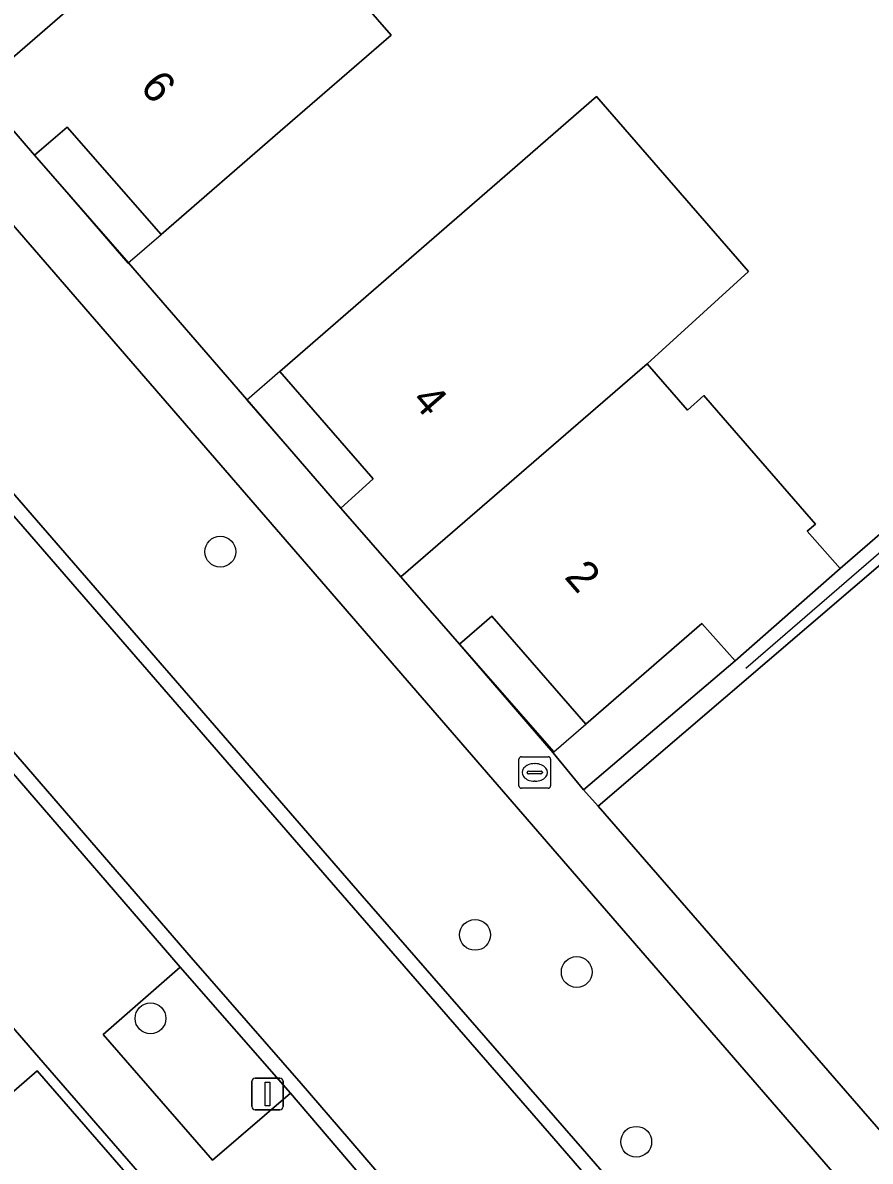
# Model space of a CAD drawing. Extents: x 155887 to 156869, y 383880 to 384678.
# Drawn here: x 156249.09 to 156275.97, y 384107.68 to 384143.78 of the extents above; entities that cross this region are included whole.
import ezdxf

# ---------------------------------------------------------------- set-up
doc = ezdxf.new("R2010")
doc.units = 0
for name, color, linetype in [('IMGEO_Berm_groen', 7, 'Continuous'), ('IMGEO_Boom', 7, 'Continuous'), ('IMGEO_Brandkraan', 7, 'Continuous'), ('IMGEO_Erf', 7, 'Continuous'), ('IMGEO_Groenvoorziening', 7, 'Continuous'), ('IMGEO_Haag', 7, 'Continuous'), ('IMGEO_Hek', 7, 'Continuous'), ('IMGEO_Lichtmast', 7, 'Continuous'), ('IMGEO_Pand', 7, 'Continuous'), ('IMGEO_Pand_nummerreeks', 7, 'Continuous'), ('IMGEO_Pand_overbouw', 7, 'Continuous'), ('IMGEO_Rijbaan_lokaal_gesloten', 7, 'Continuous'), ('IMGEO_Rijbaan_lokaal_open', 7, 'Continuous'), ('IMGEO_Voetpad_open', 7, 'Continuous')]:
    doc.layers.add(name, color=color, linetype=linetype)

msp = doc.modelspace()

# ---------------------------------------------------------------- linework, layer by layer
at = {"layer": 'IMGEO_Berm_groen'}
for points in [[(156240.218, 384147.268), (156236.004, 384143.601), (156236.378, 384143.165), (156259.369, 384116.661), (156259.86, 384116.097), (156266.847, 384108.071), (156270.265, 384104.121), (156274.816, 384099.002), (156277.067, 384096.295), (156281.229, 384099.923), (156277.633, 384104.037), (156267.33, 384115.942)], [(156254.089, 384113.836), (156251.641, 384111.7), (156255.109, 384107.715), (156257.579, 384109.84)]]:
    msp.add_lwpolyline(points, close=True, dxfattribs=at)
at = {"layer": 'IMGEO_Boom'}
for centre in [(156255.357, 384127.006), (156263.435, 384114.858), (156266.66, 384113.679), (156253.144, 384112.211), (156268.546, 384108.298)]:
    msp.add_circle(centre, 0.489, dxfattribs=at)
at = {"layer": 'IMGEO_Brandkraan'}
for p, q in [((156264.828, 384119.582), (156264.828, 384120.434)), ((156264.903, 384120.508), (156265.755, 384120.508)), ((156265.316, 384120.288), (156265.341, 384120.288)), ((156265.829, 384120.434), (156265.829, 384119.582)), ((156265.087, 384120.002), (156265.087, 384120.014)), ((156265.525, 384119.965), (156265.127, 384119.965)), ((156265.13, 384120.051), (156265.528, 384120.051)), ((156265.571, 384120.014), (156265.571, 384120.002)), ((156265.339, 384119.728), (156265.314, 384119.728)), ((156265.755, 384119.508), (156264.903, 384119.508))]:
    msp.add_line(p, q, dxfattribs=at)
for points in [[(156264.828, 384119.582), (156264.828, 384120.434)], [(156264.903, 384120.508), (156265.755, 384120.508)], [(156265.829, 384120.434), (156265.829, 384119.582)], [(156265.755, 384119.508), (156264.903, 384119.508)]]:
    msp.add_lwpolyline(points, dxfattribs=at)
for centre, radius, start, end in [((156264.905, 384120.432), 0.0765, 91.552, 178.448), ((156264.905, 384120.432), 0.0765, 91.552, 178.448), ((156265.753, 384120.432), 0.0765, 1.552, 88.448), ((156265.753, 384120.432), 0.0765, 1.552, 88.448), ((156265.127, 384120.011), 0.0403, 85.8775, 175.7526), ((156265.124, 384120.001), 0.0366, 178.938, 274.7102), ((156265.528, 384120.008), 0.043, 264.8664, 352.4533), ((156265.532, 384120.013), 0.0386, 1.7309, 96.639), ((156264.905, 384119.584), 0.0765, 181.552, 268.448), ((156264.905, 384119.584), 0.0765, 181.552, 268.448), ((156265.753, 384119.584), 0.0765, 271.552, 358.448), ((156265.753, 384119.584), 0.0765, 271.552, 358.448)]:
    msp.add_arc(centre, radius, start, end, dxfattribs=at)
for centre, major_axis, ratio, start_param, end_param in [((156265.315, 384120.008), (-0.387, 0.002), 0.722429, 4.712389, 7.853982), ((156265.34, 384120.008), (-0.39, 0.002), 0.717154, 1.570796, 4.712389)]:
    msp.add_ellipse(centre, major_axis=major_axis, ratio=ratio, start_param=start_param, end_param=end_param, dxfattribs=at)
at = {"layer": 'IMGEO_Erf'}
for points in [[(156257.239, 384147.455), (156260.775, 384143.382), (156257.259, 384140.338), (156253.479, 384137.064), (156250.507, 384140.471), (156249.466, 384139.578), (156252.45, 384136.162), (156256.203, 384131.83), (156259.179, 384128.391), (156260.205, 384129.318), (156257.244, 384132.72), (156261.019, 384136), (156264.533, 384139.053), (156267.287, 384141.445), (156272.108, 384135.896), (156268.895, 384132.962), (156270.167, 384131.497), (156270.694, 384131.955), (156270.951, 384131.658), (156274.229, 384127.882), (156273.966, 384127.653), (156275.017, 384126.47), (156285.523, 384135.566)], [(156245.439, 384106.973), (156249.554, 384110.547), (156253.551, 384105.953)]]:
    msp.add_lwpolyline(points, dxfattribs=at)
for points in [[(156233.788, 384073.174), (156236.052, 384075.143), (156235.843, 384075.385), (156236.084, 384075.595), (156236.293, 384075.353), (156236.363, 384075.42), (156236.657, 384075.088), (156237.409, 384075.743), (156244.556, 384081.969), (156245.305, 384082.622), (156261.783, 384096.974), (156257.057, 384102.381), (156253.783, 384106.157), (156249.606, 384110.968), (156241.618, 384120.183), (156237.428, 384125.007), (156235.411, 384127.346), (156228.952, 384134.784), (156195.288, 384105.561), (156189.338, 384100.396), (156193.713, 384095.326), (156201.684, 384086.153), (156205.864, 384081.345), (156221.93, 384062.847)], [(156266.876, 384119.462), (156271.681, 384123.545), (156270.63, 384124.728), (156266.943, 384121.536), (156263.965, 384124.961), (156262.942, 384124.079), (156265.908, 384120.63)]]:
    msp.add_lwpolyline(points, close=True, dxfattribs=at)
at = {"layer": 'IMGEO_Groenvoorziening'}
msp.add_lwpolyline([(156326.352, 384144.787), (156313.86, 384159.026), (156310.054, 384155.821), (156309.837, 384153.771), (156304.318, 384148.926), (156302.21, 384148.793), (156267.335, 384118.935), (156279.529, 384104.91), (156282.76, 384101.221), (156290.137, 384107.648), (156289.798, 384108.054), (156287.894, 384110.269), (156286.194, 384108.79), (156285.365, 384108.034), (156279.45, 384114.852), (156280.248, 384115.585), (156278.601, 384117.467), (156279.154, 384117.948), (156278.902, 384119.947)], dxfattribs=at)
msp.add_lwpolyline([(156285.523, 384135.566), (156275.017, 384126.47), (156271.681, 384123.545), (156266.876, 384119.462), (156267.335, 384118.935), (156302.21, 384148.793), (156302.31, 384148.879), (156302.003, 384149.234), (156301.694, 384149.592), (156291.575, 384140.774), (156288.549, 384138.17)], close=True, dxfattribs=at)
at = {"layer": 'IMGEO_Haag'}
msp.add_lwpolyline([(156285.523, 384135.566), (156275.017, 384126.47), (156271.681, 384123.545), (156266.876, 384119.462), (156267.335, 384118.935), (156302.21, 384148.793), (156302.31, 384148.879), (156302.003, 384149.234), (156301.694, 384149.592), (156291.575, 384140.774), (156288.549, 384138.17)], close=True, dxfattribs=at)
at = {"layer": 'IMGEO_Hek'}
msp.add_lwpolyline([(156302.003, 384149.234), (156272.024, 384123.309)], dxfattribs=at)
at = {"layer": 'IMGEO_Lichtmast'}
for p, q in [((156256.36, 384109.415), (156256.36, 384110.215)), ((156256.36, 384110.215), (156256.36, 384109.415)), ((156256.46, 384110.315), (156257.25, 384110.315)), ((156257.25, 384110.315), (156256.46, 384110.315)), ((156257.35, 384110.215), (156257.35, 384109.415)), ((156257.35, 384109.415), (156257.35, 384110.215)), ((156257.25, 384109.315), (156256.46, 384109.315)), ((156256.46, 384109.315), (156257.25, 384109.315))]:
    msp.add_line(p, q, dxfattribs=at)
msp.add_lwpolyline([(156256.78, 384110.19), (156256.93, 384110.19), (156256.93, 384109.44), (156256.78, 384109.44), (156256.78, 384110.19)], dxfattribs=at)
for centre, start, end in [((156256.46, 384110.215), 90, 180), ((156256.46, 384110.215), 90, 180), ((156257.25, 384110.215), 0, 90), ((156257.25, 384110.215), 360, 90), ((156256.46, 384109.415), 180, 270), ((156256.46, 384109.415), 180, 270), ((156257.25, 384109.415), 270, 0), ((156257.25, 384109.415), 270, 0)]:
    msp.add_arc(centre, 0.1, start, end, dxfattribs=at)
at = {"layer": 'IMGEO_Pand'}
for points in [[(156255.441, 384148.461), (156258.292, 384150.921), (156252.385, 384157.809), (156249.761, 384155.539), (156246.433, 384152.66), (156247.48, 384151.439), (156243.797, 384148.229), (156246.756, 384144.827), (156245.72, 384143.913), (156247.639, 384141.692)], [(156255.441, 384148.461), (156247.639, 384141.692), (156249.466, 384139.578), (156250.507, 384140.471), (156253.479, 384137.064), (156257.259, 384140.338), (156260.775, 384143.382), (156257.239, 384147.455), (156256.712, 384146.997)], [(156268.895, 384132.962), (156272.108, 384135.896), (156267.287, 384141.445), (156264.533, 384139.053), (156261.019, 384136), (156257.244, 384132.72), (156260.205, 384129.318), (156259.179, 384128.391), (156261.085, 384126.207)], [(156261.085, 384126.207), (156262.942, 384124.079), (156263.965, 384124.961), (156266.943, 384121.536), (156270.63, 384124.728), (156271.681, 384123.545), (156275.017, 384126.47), (156273.966, 384127.653), (156274.229, 384127.882), (156270.951, 384131.658), (156270.694, 384131.955), (156270.167, 384131.497), (156268.895, 384132.962)], [(156253.551, 384105.953), (156249.554, 384110.547), (156245.439, 384106.973), (156245.253, 384107.188), (156243.249, 384109.497), (156240.864, 384107.428), (156242.561, 384105.472), (156239.608, 384102.916), (156239.708, 384102.8), (156236.789, 384100.268), (156240.961, 384095.484), (156243.868, 384098.005), (156243.979, 384097.877), (156249.322, 384102.511), (156249.439, 384102.376)]]:
    msp.add_lwpolyline(points, close=True, dxfattribs=at)
at = {"layer": 'IMGEO_Pand_overbouw'}
for points in [[(156253.479, 384137.064), (156250.507, 384140.471), (156249.466, 384139.578), (156252.427, 384136.152)], [(156260.205, 384129.318), (156257.244, 384132.72), (156256.196, 384131.809), (156259.179, 384128.391)], [(156266.943, 384121.536), (156263.965, 384124.961), (156262.942, 384124.079), (156265.928, 384120.657)]]:
    msp.add_lwpolyline(points, close=True, dxfattribs=at)
at = {"layer": 'IMGEO_Rijbaan_lokaal_gesloten'}
msp.add_lwpolyline([(156235.655, 384143.297), (156235.555, 384143.21), (156231.878, 384140.144), (156233.823, 384137.913), (156236.835, 384134.451), (156242.248, 384128.205), (156249.071, 384120.349), (156254.436, 384114.138), (156257.926, 384110.141), (156259.428, 384108.395), (156261.774, 384105.668), (156266.212, 384100.578), (156267.255, 384101.508), (156267.705, 384101.909), (156268.531, 384102.646), (156268.884, 384102.961), (156269.874, 384103.844), (156265.798, 384108.566), (156259.022, 384116.36)], close=True, dxfattribs=at)
at = {"layer": 'IMGEO_Rijbaan_lokaal_open'}
for points in [[(156236.378, 384143.165), (156236.004, 384143.601), (156235.655, 384143.297), (156259.022, 384116.36), (156265.798, 384108.566), (156269.874, 384103.844), (156270.265, 384104.121), (156266.847, 384108.071), (156259.86, 384116.097), (156259.369, 384116.661)], [(156231.878, 384140.144), (156231.541, 384139.83), (156233.476, 384137.611), (156236.488, 384134.15), (156241.9, 384127.903), (156248.723, 384120.048), (156254.089, 384113.836), (156257.579, 384109.84), (156260.59, 384106.325), (156261.455, 384105.344), (156265.865, 384100.248), (156266.212, 384100.578), (156261.774, 384105.668), (156259.428, 384108.395), (156257.926, 384110.141), (156254.436, 384114.138), (156249.071, 384120.349), (156242.248, 384128.205), (156236.835, 384134.451), (156233.823, 384137.913)]]:
    msp.add_lwpolyline(points, close=True, dxfattribs=at)
at = {"layer": 'IMGEO_Voetpad_open'}
msp.add_lwpolyline([(156242.753, 384147.346), (156241.709, 384148.549), (156240.218, 384147.268), (156267.33, 384115.942), (156277.633, 384104.037), (156281.229, 384099.923), (156282.76, 384101.221), (156279.529, 384104.91), (156267.335, 384118.935), (156266.876, 384119.462), (156265.908, 384120.63), (156262.942, 384124.079), (156261.085, 384126.207), (156259.179, 384128.391), (156256.203, 384131.83), (156252.45, 384136.162), (156249.466, 384139.578), (156247.639, 384141.692), (156245.72, 384143.913)], close=True, dxfattribs=at)
msp.add_lwpolyline([(156225.054, 384139.316), (156227.956, 384135.922), (156228.952, 384134.784), (156235.411, 384127.346), (156237.428, 384125.007), (156241.618, 384120.183), (156249.606, 384110.968), (156253.783, 384106.157), (156257.057, 384102.381), (156261.783, 384096.974), (156261.927, 384096.809), (156266.381, 384091.712), (156267.907, 384093.026), (156263.479, 384098.12), (156258.145, 384104.257), (156260.59, 384106.325), (156257.579, 384109.84), (156255.109, 384107.715), (156251.641, 384111.7), (156254.089, 384113.836), (156248.723, 384120.048)], dxfattribs=at)

# ---------------------------------------------------------------- texts
at = {"layer": 'IMGEO_Pand_nummerreeks'}
for s, rotation, p in [('6', 310.931, (156252.781, 384141.715)), ('4', 310.9319, (156261.392, 384131.783)), ('2', 310.9325, (156266.24, 384126.193))]:
    msp.add_text(s, height=1, rotation=rotation, dxfattribs=at).set_placement(p)

doc.saveas('drawing.dxf')
